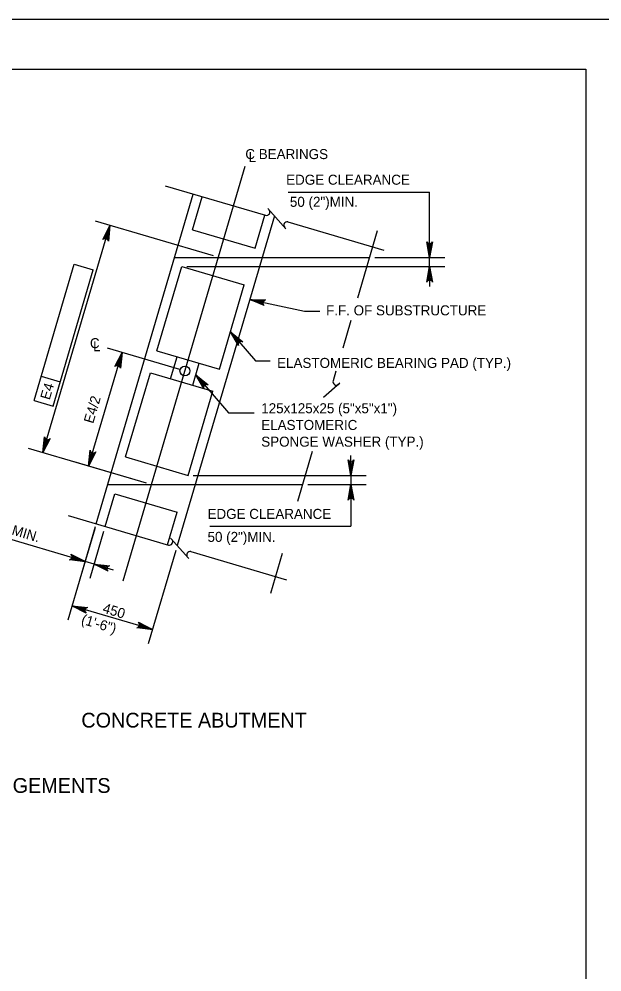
# Model space of a CAD drawing. Extents: x 638268 to 640277, y 295465 to 298435.
# Drawn here: x 639932.9 to 640107.3, y 298150.4 to 298435.5 of the extents above; entities that cross this region are included whole.
import ezdxf

# ---------------------------------------------------------------- set-up
doc = ezdxf.new("R2010")
doc.units = 0
for name, color, linetype in [('2', 7, 'Continuous'), ('3', 7, 'Continuous'), ('4', 7, 'Continuous'), ('7', 7, 'Continuous'), ('PLT-BNDY', 7, 'Continuous')]:
    doc.layers.add(name, color=color, linetype=linetype)

msp = doc.modelspace()

# ---------------------------------------------------------------- linework, layer by layer
at = {"layer": '2'}
for p, q in [((639316.46, 298420.46), (640102.46, 298420.46)), ((640102.46, 298420.46), (640102.46, 297856.46))]:
    msp.add_line(p, q, dxfattribs=at)
at = {"layer": '3'}
for p, q in [((639976.64, 298385.58), (640006.65, 298376.74)), ((639956, 298284.45), (639985.06, 298383.1)), ((640007.35, 298378.81), (640012.76, 298372.67)), ((640009.31, 298376.59), (639980.25, 298277.94)), ((640013.36, 298374.77), (640042.04, 298366.32)), ((639984.84, 298372.42), (640003.53, 298366.91)), ((640040.1, 298372.12), (640034.17, 298351.98)), ((639979.48, 298364.16), (640037.75, 298364.16)), ((639981.59, 298361.4), (640000.29, 298355.9)), ((640032.19, 298345.26), (640029.75, 298337)), ((639974.18, 298336.22), (639992.87, 298330.72)), ((639972.23, 298329.62), (639990.93, 298324.11)), ((640027.74, 298330.15), (640026.88, 298327.24)), ((640028.94, 298326.55), (640024.04, 298322.22)), ((640020.65, 298306.11), (640016.22, 298291.07)), ((639964.82, 298304.44), (639983.51, 298298.93)), ((639959.46, 298296.18), (640017.73, 298296.18)), ((639961.57, 298293.42), (639980.27, 298287.92)), ((639947.59, 298286.93), (639977.6, 298278.09)), ((639978.29, 298280.16), (639983.71, 298274.02)), ((639984.31, 298276.12), (640012.99, 298267.67)), ((640011.67, 298275.6), (640008.14, 298263.61))]:
    msp.add_line(p, q, dxfattribs=at)
for centre, start, end in [((640006.95, 298377.72), 253.588, 43.588), ((640013.17, 298373.76), 78.9166, 221.4552), ((640027.86, 298326.95), 163.588, 313.588), ((639977.89, 298279.08), 253.588, 43.588), ((639984.11, 298275.11), 78.9166, 221.4552)]:
    msp.add_arc(centre, 1.02, start, end, dxfattribs=at)
at = {"layer": '4'}
for p, q in [((639964.05, 298267.37), (640000.6, 298391.45)), ((640013.49, 298383.7), (640055.76, 298383.7)), ((640055.76, 298367.16), (640055.76, 298383.7)), ((639991.06, 298364.6), (639955.81, 298374.98)), ((639940.1, 298305.73), (639960.13, 298373.71)), ((640039.32, 298364.16), (640060.26, 298364.16)), ((640055.76, 298361.4), (640055.76, 298364.16)), ((639937.44, 298321.33), (639949.45, 298362.12)), ((639943.1, 298319.67), (639955.11, 298360.45)), ((639949.45, 298362.12), (639955.11, 298360.45)), ((639983.15, 298361.4), (640060.26, 298361.4)), ((640055.76, 298358.4), (640055.76, 298355.4)), ((640018.31, 298348.09), (640022.87, 298348.09)), ((639953.73, 298301.72), (639963.74, 298335.71)), ((639981.05, 298330.61), (639959.43, 298336.98)), ((640003.66, 298333.25), (640008.01, 298333.25)), ((639939.57, 298328.59), (639945.24, 298326.92)), ((639937.44, 298321.33), (639943.1, 298319.67)), ((639995.57, 298317.67), (640003.23, 298317.67)), ((639971.04, 298296.62), (639935.79, 298307)), ((639971.04, 298296.62), (639949.41, 298302.99)), ((640032.23, 298301.93), (640032.23, 298304.93)), ((639985.07, 298298.93), (640036.73, 298298.93)), ((640032.23, 298298.93), (640032.23, 298296.18)), ((640019.29, 298296.18), (640036.73, 298296.18)), ((640032.23, 298293.18), (640032.23, 298283.71)), ((639952.69, 298273.2), (639914.76, 298284.37)), ((639955.73, 298283.53), (639947.5, 298255.59)), ((639955.56, 298282.96), (639951.42, 298268.88)), ((639989.97, 298283.71), (640032.23, 298283.71)), ((639958.25, 298282.16), (639954.11, 298268.09)), ((639979.81, 298276.44), (639971.58, 298248.5)), ((639955.38, 298272.4), (639952.69, 298273.2)), ((639955.38, 298272.4), (639961.13, 298270.71)), ((639972.85, 298252.81), (639948.77, 298259.91))]:
    msp.add_line(p, q, dxfattribs=at)
for points in [[(639960.13, 298373.71), (639959.65, 298369), (639959.51, 298369.41), (639959.26, 298369.67), (639958.98, 298369.81), (639958.66, 298369.85), (639958.31, 298369.76), (639957.97, 298369.49), (639960.13, 298373.71), (639958.31, 298369.76), (639958.66, 298369.85), (639960.13, 298373.71), (639958.98, 298369.81), (639959.26, 298369.67), (639960.13, 298373.71), (639959.51, 298369.41)], [(640055.76, 298364.16), (640054.89, 298368.82), (640055.13, 298368.46), (640055.45, 298368.27), (640055.76, 298368.22), (640056.07, 298368.27), (640056.38, 298368.46), (640056.63, 298368.82), (640055.76, 298364.16), (640056.38, 298368.46), (640056.07, 298368.27), (640055.76, 298364.16), (640055.76, 298368.22), (640055.45, 298368.27), (640055.76, 298364.16), (640055.13, 298368.46)], [(640055.76, 298361.4), (640056.63, 298356.74), (640056.38, 298357.1), (640056.07, 298357.29), (640055.76, 298357.34), (640055.45, 298357.29), (640055.13, 298357.1), (640054.89, 298356.74), (640055.76, 298361.4), (640055.13, 298357.1), (640055.45, 298357.29), (640055.76, 298361.4), (640055.76, 298357.34), (640056.07, 298357.29), (640055.76, 298361.4), (640056.38, 298357.1)], [(640001.93, 298351.54), (640018.31, 298348.09)], [(640001.93, 298351.54), (640006.67, 298351.44), (640006.27, 298351.27), (640006.02, 298351), (640005.9, 298350.7), (640005.89, 298350.39), (640006.01, 298350.04), (640006.31, 298349.73), (640001.93, 298351.54), (640006.01, 298350.04), (640005.89, 298350.39), (640001.93, 298351.54), (640005.9, 298350.7), (640006.02, 298351), (640001.93, 298351.54), (640006.27, 298351.27)], [(639996.15, 298341.86), (640003.66, 298333.25)], [(639996.15, 298341.86), (639999.87, 298338.92), (639999.45, 298339.02), (639999.09, 298338.96), (639998.82, 298338.79), (639998.62, 298338.55), (639998.51, 298338.2), (639998.55, 298337.77), (639996.15, 298341.86), (639998.51, 298338.2), (639998.62, 298338.55), (639996.15, 298341.86), (639998.82, 298338.79), (639999.09, 298338.96), (639996.15, 298341.86), (639999.45, 298339.02)], [(639963.74, 298335.71), (639963.27, 298330.99), (639963.13, 298331.41), (639962.88, 298331.67), (639962.6, 298331.81), (639962.28, 298331.85), (639961.93, 298331.76), (639961.59, 298331.48), (639963.74, 298335.71), (639961.93, 298331.76), (639962.28, 298331.85), (639963.74, 298335.71), (639962.6, 298331.81), (639962.88, 298331.67), (639963.74, 298335.71), (639963.13, 298331.41)], [(639985.8, 298328.99), (639995.57, 298317.67)], [(639985.8, 298328.99), (639989.5, 298326.03), (639989.08, 298326.14), (639988.72, 298326.08), (639988.45, 298325.92), (639988.25, 298325.67), (639988.13, 298325.33), (639988.18, 298324.89), (639985.8, 298328.99), (639988.13, 298325.33), (639988.25, 298325.67), (639985.8, 298328.99), (639988.45, 298325.92), (639988.72, 298326.08), (639985.8, 298328.99), (639989.08, 298326.14)], [(639940.1, 298305.73), (639940.58, 298310.45), (639940.72, 298310.03), (639940.97, 298309.77), (639941.25, 298309.63), (639941.57, 298309.59), (639941.92, 298309.68), (639942.26, 298309.96), (639940.1, 298305.73), (639941.92, 298309.68), (639941.57, 298309.59), (639940.1, 298305.73), (639941.25, 298309.63), (639940.97, 298309.77), (639940.1, 298305.73), (639940.72, 298310.03)], [(639953.73, 298301.72), (639954.21, 298306.43), (639954.35, 298306.02), (639954.59, 298305.76), (639954.88, 298305.62), (639955.19, 298305.58), (639955.55, 298305.67), (639955.89, 298305.94), (639953.73, 298301.72), (639955.55, 298305.67), (639955.19, 298305.58), (639953.73, 298301.72), (639954.88, 298305.62), (639954.59, 298305.76), (639953.73, 298301.72), (639954.35, 298306.02)], [(640032.23, 298298.93), (640031.36, 298303.6), (640031.61, 298303.24), (640031.92, 298303.05), (640032.23, 298303), (640032.55, 298303.05), (640032.86, 298303.24), (640033.11, 298303.6), (640032.23, 298298.93), (640032.86, 298303.24), (640032.55, 298303.05), (640032.23, 298298.93), (640032.23, 298303), (640031.92, 298303.05), (640032.23, 298298.93), (640031.61, 298303.24)], [(640032.23, 298296.18), (640033.11, 298291.52), (640032.86, 298291.88), (640032.55, 298292.06), (640032.23, 298292.12), (640031.92, 298292.06), (640031.61, 298291.88), (640031.36, 298291.52), (640032.23, 298296.18), (640031.61, 298291.88), (640031.92, 298292.06), (640032.23, 298296.18), (640032.23, 298292.12), (640032.55, 298292.06), (640032.23, 298296.18), (640032.86, 298291.88)], [(639952.69, 298273.2), (639947.97, 298273.67), (639948.39, 298273.81), (639948.65, 298274.06), (639948.79, 298274.34), (639948.83, 298274.66), (639948.74, 298275.01), (639948.46, 298275.35), (639952.69, 298273.2), (639948.74, 298275.01), (639948.83, 298274.66), (639952.69, 298273.2), (639948.79, 298274.34), (639948.65, 298274.06), (639952.69, 298273.2), (639948.39, 298273.81)], [(639955.38, 298272.4), (639960.09, 298271.92), (639959.68, 298271.79), (639959.41, 298271.54), (639959.28, 298271.26), (639959.24, 298270.94), (639959.33, 298270.59), (639959.6, 298270.25), (639955.38, 298272.4), (639959.33, 298270.59), (639959.24, 298270.94), (639955.38, 298272.4), (639959.28, 298271.26), (639959.41, 298271.54), (639955.38, 298272.4), (639959.68, 298271.79)], [(639948.77, 298259.91), (639953.49, 298259.43), (639953.08, 298259.29), (639952.81, 298259.04), (639952.67, 298258.76), (639952.63, 298258.44), (639952.72, 298258.09), (639953, 298257.75), (639948.77, 298259.91), (639952.72, 298258.09), (639952.63, 298258.44), (639948.77, 298259.91), (639952.67, 298258.76), (639952.81, 298259.04), (639948.77, 298259.91), (639953.08, 298259.29)], [(639972.85, 298252.81), (639968.13, 298253.29), (639968.55, 298253.43), (639968.81, 298253.68), (639968.95, 298253.96), (639968.99, 298254.28), (639968.9, 298254.63), (639968.63, 298254.97), (639972.85, 298252.81), (639968.9, 298254.63), (639968.99, 298254.28), (639972.85, 298252.81), (639968.95, 298253.96), (639968.81, 298253.68), (639972.85, 298252.81), (639968.55, 298253.43)]]:
    msp.add_lwpolyline(points, dxfattribs=at)
for points in [[(639958.8, 298370.97), (639959.76, 298370.69), (639960.13, 298373.71)], [(640055.26, 298367.16), (640056.26, 298367.16), (640055.76, 298364.16)], [(640055.26, 298358.4), (640056.26, 298358.4), (640055.76, 298361.4)], [(640001.93, 298351.54), (640004.81, 298350.68), (640004.92, 298351.17)], [(639996.15, 298341.86), (639997.94, 298339.43), (639998.31, 298339.76)], [(639962.42, 298332.97), (639963.38, 298332.69), (639963.74, 298335.71)], [(639985.8, 298328.99), (639987.57, 298326.56), (639987.94, 298326.88)], [(639940.47, 298308.75), (639941.43, 298308.47), (639940.1, 298305.73)], [(639954.1, 298304.74), (639955.06, 298304.45), (639953.73, 298301.72)], [(640031.73, 298301.93), (640032.73, 298301.93), (640032.23, 298298.93)], [(640031.73, 298293.18), (640032.73, 298293.18), (640032.23, 298296.18)], [(639949.95, 298274.52), (639949.67, 298273.56), (639952.69, 298273.2)], [(639958.4, 298272.04), (639958.11, 298271.08), (639955.38, 298272.4)], [(639951.79, 298259.54), (639951.51, 298258.58), (639948.77, 298259.91)], [(639970.11, 298254.14), (639969.83, 298253.18), (639972.85, 298252.81)]]:
    msp.add_lwpolyline(points, close=True, dxfattribs=at)
at = {"layer": '7'}
for p, q in [((639984.84, 298372.42), (639987.75, 298382.31)), ((640003.53, 298366.91), (640006.45, 298376.8)), ((639974.18, 298336.22), (639981.59, 298361.4)), ((639992.87, 298330.72), (640000.29, 298355.9)), ((639978.27, 298327.84), (639980.22, 298334.45)), ((639984.88, 298325.89), (639986.83, 298332.5)), ((639964.82, 298304.44), (639972.23, 298329.62)), ((639983.51, 298298.93), (639990.93, 298324.11)), ((639958.69, 298283.66), (639961.57, 298293.42)), ((639977.39, 298278.16), (639980.27, 298287.92))]:
    msp.add_line(p, q, dxfattribs=at)
msp.add_circle((639982.55, 298330.17), 1.48, dxfattribs=at)
at = {"layer": 'PLT-BNDY'}
msp.add_lwpolyline([(639276.46, 298435.46), (640117.46, 298435.46), (640117.46, 297841.46), (639276.46, 297841.46)], close=True, dxfattribs=at)

# ---------------------------------------------------------------- texts
at = {"layer": '3'}
for s, p in [('CONCRETE ABUTMENT', (639951.57, 298223.48)), ('ELASTOMERIC BEARING PAD ARRANGEMENTS', (639824.06, 298203.94))]:
    msp.add_text(s, height=4.4292, dxfattribs=at).set_placement(p)
at = {"layer": '4'}
for s, p in [('C BEARINGS', (640000.63, 298393.56)), ('L', (640001.58, 298392.65)), ('EDGE CLEARANCE', (640012.84, 298385.89)), ('50 (2")MIN.', (640013.96, 298379.28)), ('F.F. OF SUBSTRUCTURE', (640024.79, 298346.81)), ('C', (639954.15, 298336.99)), ('L', (639955.1, 298336.08)), ('ELASTOMERIC BEARING PAD (TYP.)', (640010.13, 298331.08)), ('125x125x25 (5"x5"x1")', (640005.39, 298317.52)), ('ELASTOMERIC', (640005.39, 298312.52)), ('SPONGE WASHER (TYP.)', (640005.39, 298307.52)), ('EDGE CLEARANCE', (639989.32, 298285.91)), ('50 (2")MIN.', (639989.32, 298279.03))]:
    msp.add_text(s, height=3, dxfattribs=at).set_placement(p)
for s, rotation, p in [('E4', 73.5262, (639942.08, 298321.33)), ('E4/2', 73.588, (639955.1, 298314.26)), ('50 (2")MIN.', 343.588, (639919.13, 298284.63)), ('450', 343.588, (639957.73, 298257.92)), ('(1\'-6")', 343.588, (639951.32, 298254.59))]:
    msp.add_text(s, height=3, rotation=rotation, dxfattribs=at).set_placement(p)

doc.saveas('drawing.dxf')
